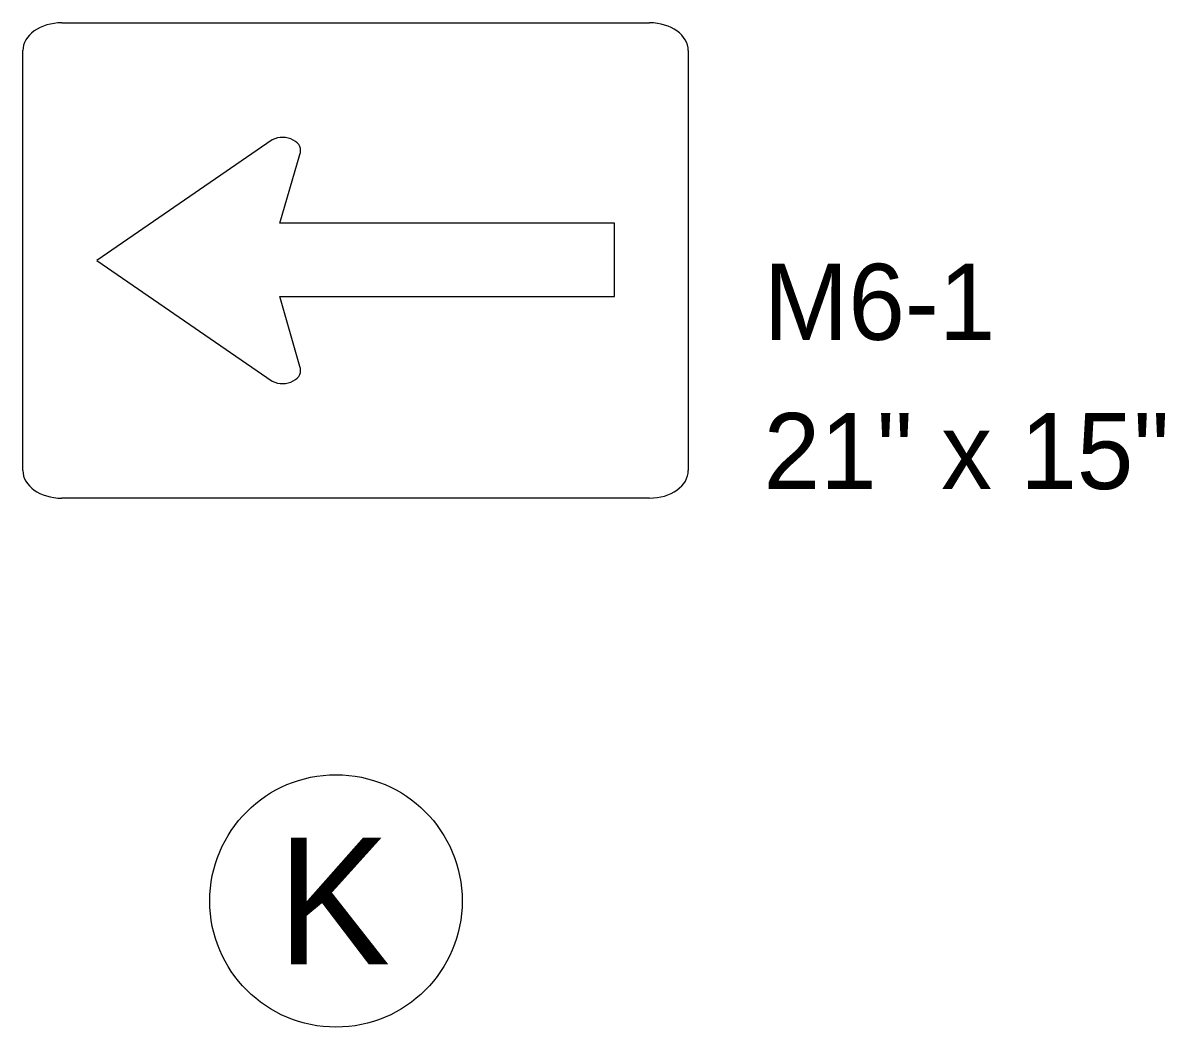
# Model space of a CAD drawing. Extents: x 2157572 to 5059327, y 715220 to 1674494.
# Drawn here: x 2165644.5 to 2166082.7, y 720621.7 to 721007.1 of the extents above; entities that cross this region are included whole.
import ezdxf

# ---------------------------------------------------------------- set-up
doc = ezdxf.new("R2010")
doc.units = 0
for name, color, linetype in [('Exist Cultural Church Label', 7, 'Continuous'), ('Level 57', 7, 'Continuous'), ('Map Preparation County Base Legend Highway Garage or Maintenance Office', 7, 'Continuous')]:
    doc.layers.add(name, color=color, linetype=linetype)

msp = doc.modelspace()

# ---------------------------------------------------------------- linework, layer by layer
at = {"layer": 'Exist Cultural Church Label'}
msp.add_circle((2165764.6, 720670.16), 48.43, dxfattribs=at)
at = {"layer": 'Level 57'}
for p, q in [((2165772.12, 721007.08), (2165772.12, 721007.08)), ((2165740.17, 720962.23), (2165672.89, 720915.89)), ((2165743.08, 720930.18), (2165750.68, 720956.59)), ((2165871.5, 720930.18), (2165743.08, 720930.18)), ((2165871.5, 720902.08), (2165871.5, 720930.18)), ((2165672.89, 720915.89), (2165740.17, 720869.56)), ((2165750.68, 720875.2), (2165743.1, 720902.08)), ((2165743.1, 720902.08), (2165871.5, 720902.08))]:
    msp.add_line(p, q, dxfattribs=at)
for points in [[(2165659.36, 721007.08), (2165884.89, 721007.08)], [(2165644.46, 720835.34), (2165644.46, 720996.44)], [(2165899.78, 720996.44), (2165899.78, 720835.35)], [(2165884.89, 720824.71), (2165659.36, 720824.71)]]:
    msp.add_lwpolyline(points, dxfattribs=at)
for centre, major_axis, ratio, start_param, end_param in [((2165659.35, 720996.44), (-14.89, 0), 0.714286, 4.712162, 6.283185), ((2165884.89, 720996.44), (14.89, 0), 0.714286, 0, 1.570796), ((2165744.08, 720958.12), (-6.93, 0), 0.720018, 2.830616, 5.313575), ((2165744.08, 720873.67), (-6.93, 0), 0.720018, 0.969609, 3.452568), ((2165659.35, 720835.34), (-14.89, 0), 0.714286, 0, 1.570796), ((2165884.89, 720835.35), (-14.89, 0), 0.714286, 1.570796, 3.141593)]:
    msp.add_ellipse(centre, major_axis=major_axis, ratio=ratio, start_param=start_param, end_param=end_param, dxfattribs=at)
at = {"layer": 'Map Preparation County Base Legend Highway Garage or Maintenance Office'}
msp.add_circle((2165764.6, 720670.16), 48.43, dxfattribs=at)

# ---------------------------------------------------------------- texts
at = {"layer": 'Exist Cultural Church Label'}
msp.add_text('K', height=48.63, dxfattribs=at).set_placement((2165742.01, 720645.84))
at = {"layer": 'Level 57'}
for s, p in [('M6-1', (2165928.68, 720885.45)), ('21" x 15"', (2165928.68, 720828.19))]:
    msp.add_text(s, height=29.18, rotation=360, dxfattribs=at).set_placement(p)

doc.saveas('drawing.dxf')
